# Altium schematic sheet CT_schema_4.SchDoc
size 298 x 247 mm
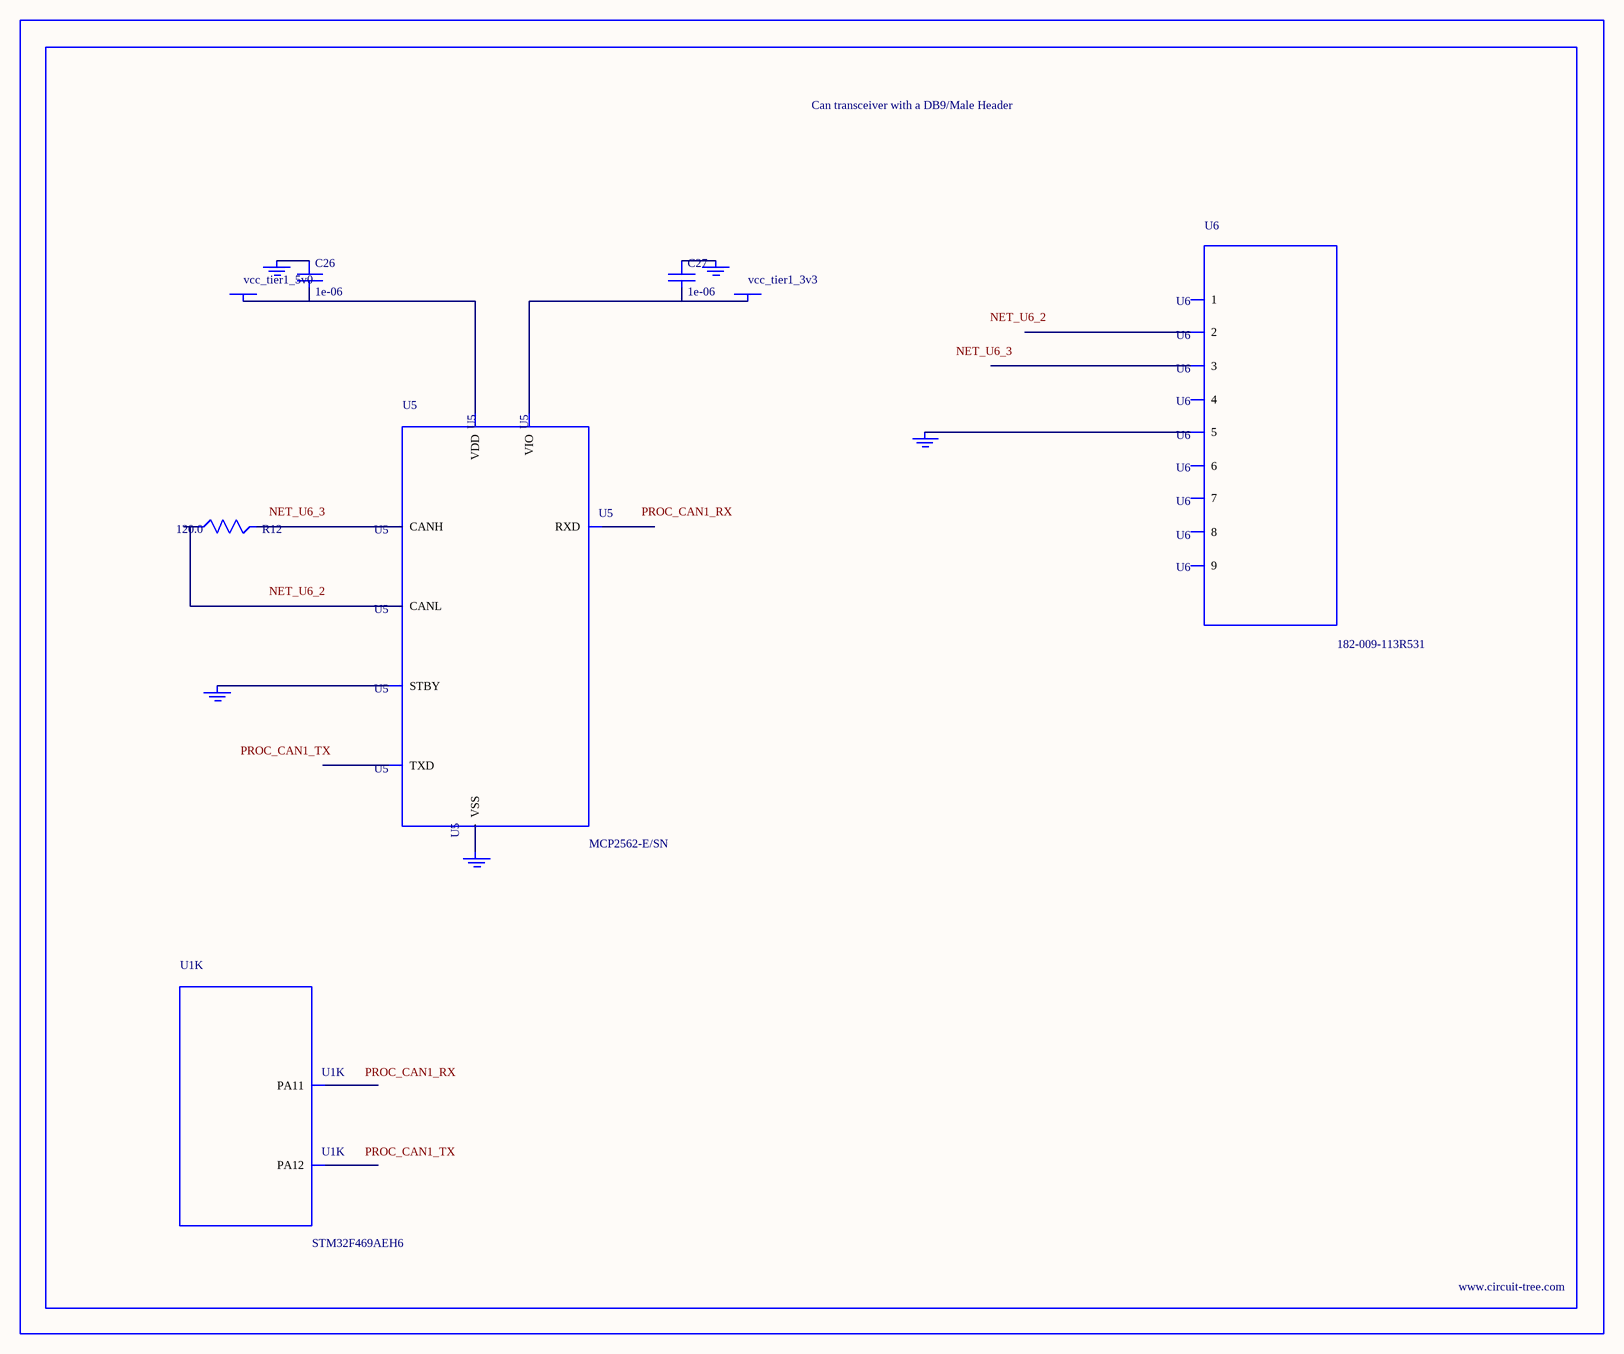
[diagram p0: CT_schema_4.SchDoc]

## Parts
BORDER3  (no value)
C26  1e-06  [C0603]
C27  1e-06  [C0603]
GND_INSTANCE_3_0  (no value)
GND_INSTANCE_3_1  (no value)
GND_INSTANCE_3_2  (no value)
GND_INSTANCE_3_3  (no value)
GND_INSTANCE_3_4  (no value)
POWER_INSTANCE_3_0  vcc_tier1_5v0
POWER_INSTANCE_3_1  vcc_tier1_3v3
R12  120.0  [R0603]
U1  STM32F469AEH6  [UFBGA169]  (part K of 14)
U5  MCP2562-E/SN  [SOIC-8]
U6  182-009-113R531  [182-009-MALE]

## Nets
NetC26_1: C26.1 GND_INSTANCE_3_0.0(GND)
NetC26_2: C26.2 POWER_INSTANCE_3_0.0(PWR) U5.3(VDD)
NetC27_1: C27.1 GND_INSTANCE_3_1.0(GND)
NetC27_2: C27.2 POWER_INSTANCE_3_1.0(PWR) U5.5(VIO)
NetGND_INSTANCE_3_2_0: GND_INSTANCE_3_2.0(GND) U5.8(STBY)
NetGND_INSTANCE_3_3_0: GND_INSTANCE_3_3.0(GND) U5.2(VSS)
NetGND_INSTANCE_3_4_0: GND_INSTANCE_3_4.0(GND) U6.5
NetR12_1: R12.1 U5.6(CANL)
NetR12_2: R12.2 U5.7(CANH)

Not connected (* = marked no-connect by the designer): U1 A12(PA12) A13(PA11); U5 1(TXD) 4(RXD); U6 1 2 3 4 6 7 8 9

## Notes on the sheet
- Labels drawn without touching a wire or pin: NET_U6_2, NET_U6_3, PROC_CAN1_RX, PROC_CAN1_TX

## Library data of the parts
BORDER3 = BORDER_PAGE3
C26 C27 = C0603C105K3RACTU
GND_INSTANCE_3_0-GND_INSTANCE_3_4 = GND
POWER_INSTANCE_3_0 POWER_INSTANCE_3_1 = PWR
R12 = RC0603JR-07120RL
